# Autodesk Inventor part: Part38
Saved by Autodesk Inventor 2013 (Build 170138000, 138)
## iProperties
Created: 2012-07
Part Number: Part38
Material: Acetal Resin, Black
Document SubType Name: Modeling
Designer: Paul
Density: 1 g/cm^3
Author: Paul
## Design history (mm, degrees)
node "User Library-Arduino Mega.SAT1"
body "Solid1"
node "Base1"
